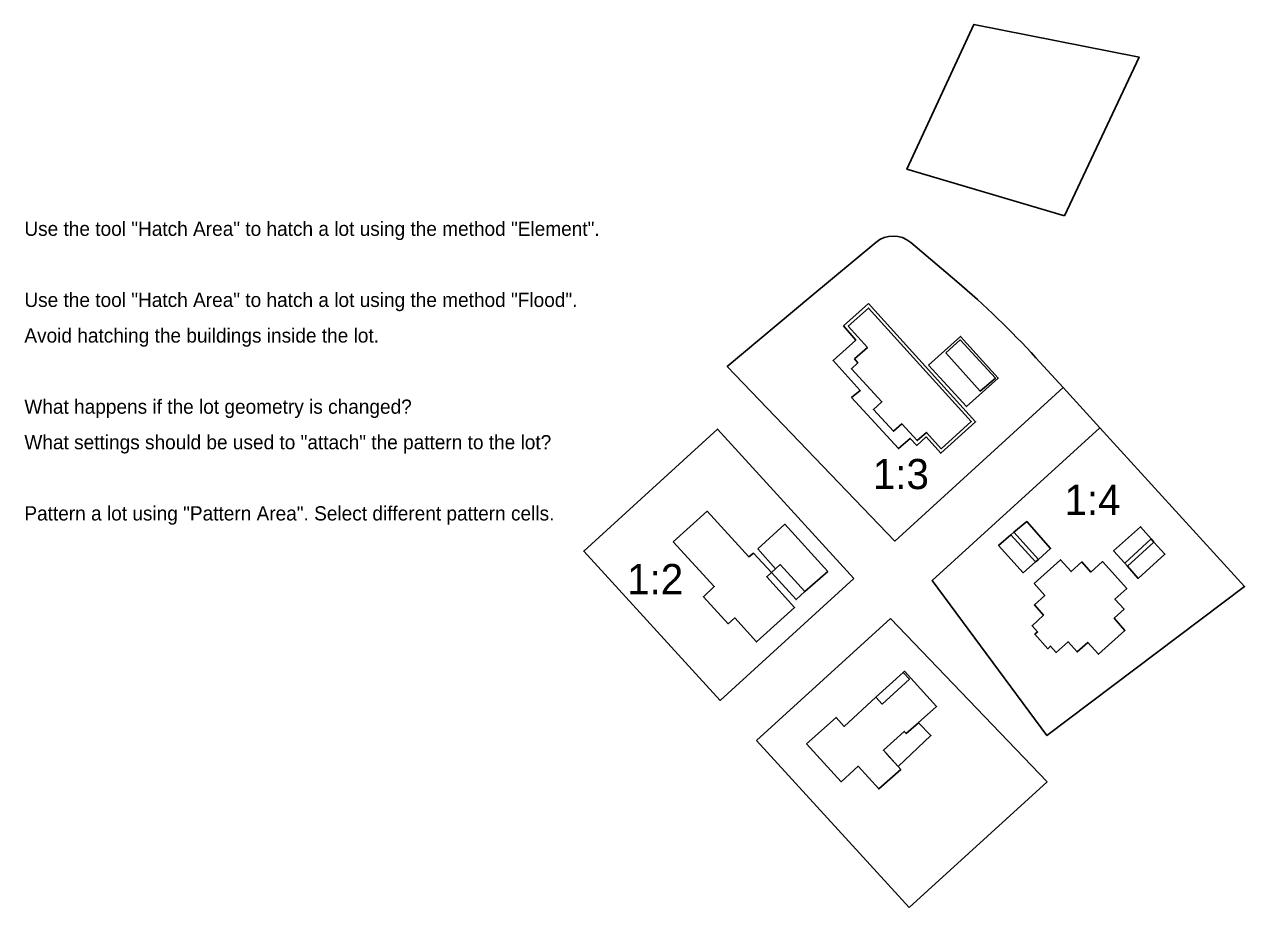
# Model space of a CAD drawing. Extents: x 1517738 to 1517940, y 6495475 to 6495622.
import ezdxf

# ---------------------------------------------------------------- set-up
doc = ezdxf.new("R2010")
doc.units = 0
for name, color, linetype in [('bostadshus', 7, 'Continuous'), ('Default', 7, 'Continuous'), ('fastighetsbeteckning', 7, 'Continuous'), ('grans', 7, 'Continuous'), ('Instruktioner', 7, 'Continuous'), ('kvartersgrans_utan_fastgr', 7, 'Continuous'), ('skarmtak', 7, 'Continuous'), ('stenmur', 7, 'Continuous'), ('uthus', 7, 'Continuous')]:
    doc.layers.add(name, color=color, linetype=linetype)

msp = doc.modelspace()

# ---------------------------------------------------------------- linework, layer by layer
at = {"layer": 'bostadshus'}
for points in [[(1517874.62, 6495571.75), (1517877.96, 6495574.75), (1517895.01, 6495555.97), (1517890.02, 6495551.43), (1517887.58, 6495554.14), (1517886.04, 6495552.78), (1517883.52, 6495555.56), (1517882.13, 6495554.34), (1517878.8, 6495557.93), (1517880.2, 6495559.23), (1517875.14, 6495564.69), (1517876.2, 6495565.67), (1517875.66, 6495566.32), (1517877.79, 6495568.23), (1517874.62, 6495571.75)], [(1517845.64, 6495535.98), (1517851.23, 6495541.07), (1517858.16, 6495533.49), (1517858.9, 6495534.11), (1517861.9, 6495530.89), (1517861.13, 6495530.21), (1517865.74, 6495525.14), (1517859.44, 6495519.42), (1517855.85, 6495523.39), (1517854.75, 6495522.42), (1517850.63, 6495526.89), (1517852.42, 6495528.58), (1517845.64, 6495535.98)], [(1517905.43, 6495529.08), (1517909.77, 6495533.03), (1517911.55, 6495531.06), (1517913.32, 6495532.66), (1517914.83, 6495530.98), (1517916.74, 6495532.74), (1517920.77, 6495528.26), (1517918.8, 6495526.5), (1517920.33, 6495524.85), (1517918.68, 6495523.35), (1517920.45, 6495521.31), (1517916.06, 6495517.37), (1517914.29, 6495519.32), (1517912.54, 6495517.75), (1517911.04, 6495519.43), (1517909.06, 6495517.64), (1517908.11, 6495518.72), (1517907.68, 6495518.27), (1517905.53, 6495520.67), (1517906, 6495521.07), (1517905.08, 6495522.1), (1517906.96, 6495523.85), (1517905.45, 6495525.54), (1517907.18, 6495527.08), (1517905.43, 6495529.08)], [(1517867.71, 6495502.51), (1517872.62, 6495506.89), (1517873.97, 6495505.41), (1517879.2, 6495510.24), (1517880.24, 6495509.1), (1517884.75, 6495513.25), (1517883.73, 6495514.34), (1517883.96, 6495514.54), (1517889.25, 6495508.7), (1517884.23, 6495504.22), (1517883.89, 6495504.58), (1517880.46, 6495501.44), (1517883.33, 6495498.26), (1517879.68, 6495495.03), (1517876.27, 6495498.8), (1517873.44, 6495496.23), (1517867.71, 6495502.51)]]:
    msp.add_lwpolyline(points, dxfattribs=at)
at = {"layer": 'Default'}
for points in [[(1517910.42, 6495590.03), (1517884.35, 6495597.77), (1517895.45, 6495621.77), (1517922.8, 6495616.35)], [(1517875.55, 6495529.94), (1517853.39, 6495509.72), (1517830.82, 6495534.46), (1517852.98, 6495554.68)]]:
    msp.add_lwpolyline(points, close=True, dxfattribs=at)
at = {"layer": 'grans'}
for p, q in [((1517905.69, 6495566.52), (1517905.69, 6495566.52)), ((1517859.45, 6495503.07), (1517881.62, 6495523.29)), ((1517881.62, 6495523.29), (1517907.56, 6495496.2)), ((1517884.73, 6495475.37), (1517859.45, 6495503.07)), ((1517907.56, 6495496.2), (1517884.73, 6495475.37))]:
    msp.add_line(p, q, dxfattribs=at)
for points in [[(1517905.69, 6495566.52), (1517910.22, 6495561.56), (1517882.32, 6495536.12), (1517854.58, 6495565.09), (1517868.41, 6495576.64), (1517879.18, 6495585.64)], [(1517884.98, 6495585.62), (1517892.59, 6495579.16), (1517892.59, 6495579.16)]]:
    msp.add_lwpolyline(points, dxfattribs=at)
for points in [[(1517916.28, 6495554.91), (1517940.28, 6495528.59), (1517907.54, 6495503.88), (1517888.55, 6495529.61)], [(1517875.55, 6495529.94), (1517853.39, 6495509.72), (1517830.82, 6495534.46), (1517852.98, 6495554.68)]]:
    msp.add_lwpolyline(points, close=True, dxfattribs=at)
for centre, radius, start, end in [((1517882.07, 6495582.19), 4.5, 49.6994, 129.8503), ((1517799.71, 6495469.81), 143.47, 42.3829, 49.656)]:
    msp.add_arc(centre, radius, start, end, dxfattribs=at)
at = {"layer": 'kvartersgrans_utan_fastgr'}
msp.add_line((1517910.22, 6495561.56), (1517916.28, 6495554.91), dxfattribs=at)
at = {"layer": 'skarmtak'}
for p, q in [((1517873.81, 6495571.82), (1517877.99, 6495575.51)), ((1517862.55, 6495531.54), (1517861.9, 6495530.89)), ((1517879.2, 6495510.24), (1517883.73, 6495514.34))]:
    msp.add_line(p, q, dxfattribs=at)
for points in [[(1517877.99, 6495575.51), (1517895.73, 6495555.9), (1517889.95, 6495550.68), (1517887.51, 6495553.38), (1517885.98, 6495551.98), (1517884.89, 6495553.13), (1517882.94, 6495551.45), (1517875.17, 6495559.91), (1517876.62, 6495561.1), (1517872.11, 6495566.04), (1517875.86, 6495569.45), (1517873.81, 6495571.82)], [(1517887.94, 6495565.3), (1517893.21, 6495570.06), (1517899.47, 6495563.14), (1517894.21, 6495558.41), (1517887.92, 6495565.27)], [(1517902.06, 6495537.6), (1517904.21, 6495539.36), (1517908.14, 6495534.89), (1517906.12, 6495533.06)], [(1517901.55, 6495537.15), (1517899.53, 6495535.37), (1517903.58, 6495530.88), (1517905.65, 6495532.67)], [(1517924.79, 6495536.47), (1517923.01, 6495538.51), (1517918.58, 6495534.5), (1517920.45, 6495532.48)], [(1517925.26, 6495535.97), (1517927.08, 6495533.98), (1517922.65, 6495529.93), (1517920.91, 6495531.98)], [(1517861.9, 6495530.89), (1517865.97, 6495526.43), (1517867.41, 6495527.75)], [(1517880.46, 6495501.44), (1517883.89, 6495504.58), (1517884.23, 6495504.22), (1517886.24, 6495506.02), (1517888.33, 6495503.88), (1517882.88, 6495498.76), (1517880.93, 6495500.92)]]:
    msp.add_lwpolyline(points, dxfattribs=at)
at = {"layer": 'stenmur'}
for p, q in [((1517901.55, 6495537.15), (1517902.06, 6495537.6)), ((1517905.65, 6495532.67), (1517901.55, 6495537.15)), ((1517906.12, 6495533.06), (1517902.06, 6495537.6)), ((1517920.45, 6495532.48), (1517924.79, 6495536.47)), ((1517920.91, 6495531.98), (1517925.26, 6495535.97)), ((1517924.79, 6495536.47), (1517925.26, 6495535.97)), ((1517905.65, 6495532.67), (1517906.12, 6495533.06)), ((1517905.7, 6495532.63), (1517905.7, 6495532.63)), ((1517920.45, 6495532.48), (1517920.91, 6495531.98))]:
    msp.add_line(p, q, dxfattribs=at)
at = {"layer": 'uthus'}
for points in [[(1517890.78, 6495567.34), (1517893.18, 6495569.48), (1517898.99, 6495563.11), (1517896.47, 6495560.98), (1517890.78, 6495567.34)], [(1517859.64, 6495534.83), (1517864.13, 6495538.92), (1517871.22, 6495531.11), (1517867.41, 6495527.75), (1517863.34, 6495532.23), (1517862.55, 6495531.54), (1517859.64, 6495534.83)]]:
    msp.add_lwpolyline(points, dxfattribs=at)

# ---------------------------------------------------------------- texts
at = {"layer": 'fastighetsbeteckning'}
for s, p in [('1:3', (1517878.69, 6495544.74)), ('1:4', (1517910.44, 6495540.46)), ('1:2', (1517837.99, 6495527.32))]:
    msp.add_text(s, height=5, rotation=0.0021, dxfattribs=at).set_placement(p)
at = {"layer": 'Instruktioner'}
for s, p in [('Use the tool "Hatch Area" to hatch a lot using the method "Element".', (1517738.14, 6495586.72)), ('Use the tool "Hatch Area" to hatch a lot using the method "Flood".', (1517738.14, 6495574.93)), ('Avoid hatching the buildings inside the lot.', (1517738.14, 6495569.03)), ('What happens if the lot geometry is changed?', (1517738.14, 6495557.23)), ('What settings should be used to "attach" the pattern to the lot?', (1517738.14, 6495551.34)), ('Pattern a lot using "Pattern Area". Select different pattern cells.', (1517738.14, 6495539.54))]:
    msp.add_text(s, height=2.3588, dxfattribs=at).set_placement(p)

doc.saveas('drawing.dxf')
